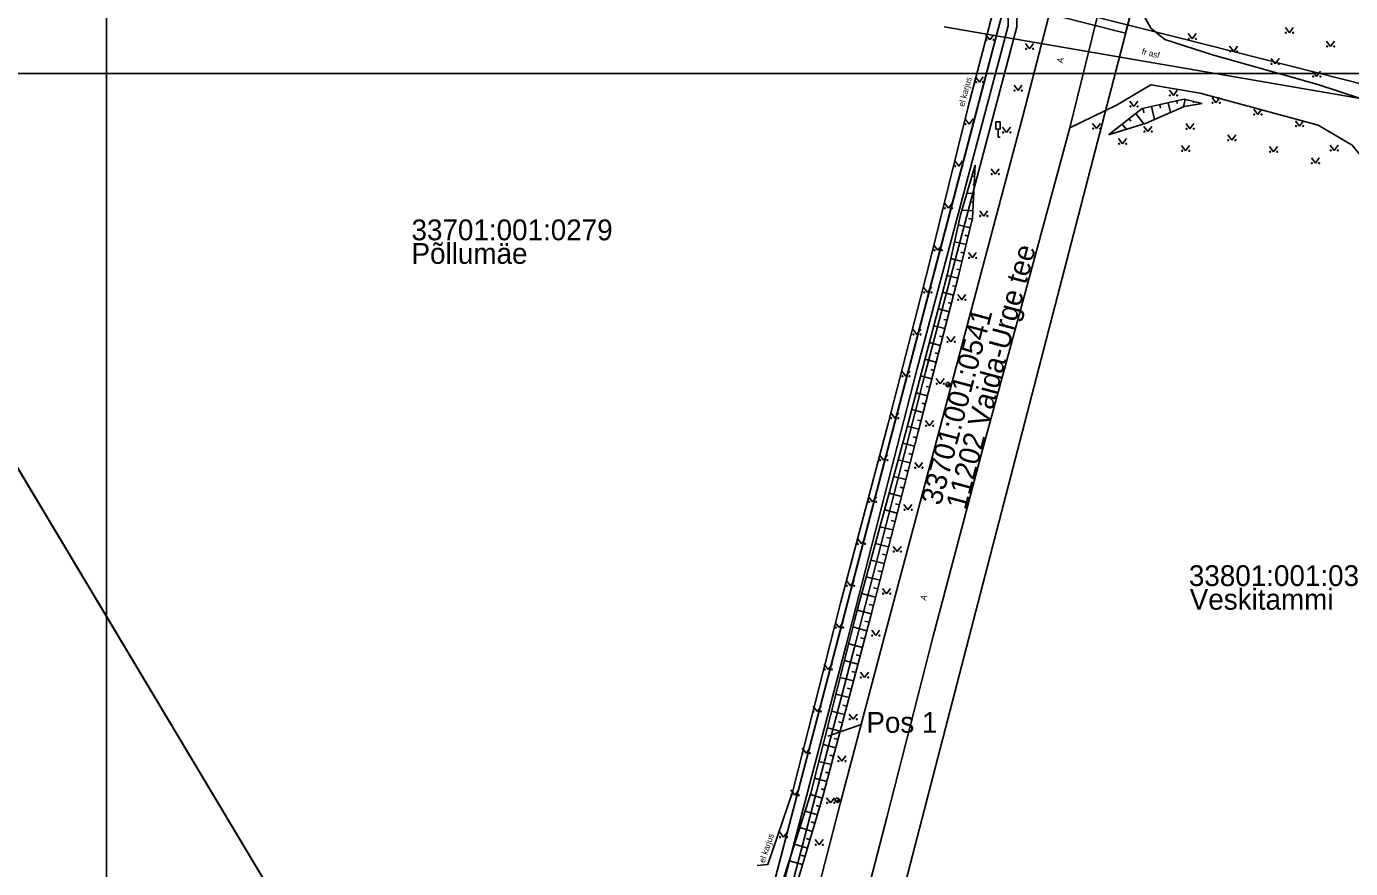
# Model space of a CAD drawing. Extents: x 554947 to 555436, y 6564938 to 6565792.
# Drawn here: x 555042.9 to 555195.6, y 6565056.2 to 6565153.3 of the extents above; entities that cross this region are included whole.
import ezdxf

# ---------------------------------------------------------------- set-up
doc = ezdxf.new("R2010")
doc.units = 0
for name, color, linetype in [('AED', 7, 'Continuous'), ('HALJASTUS', 7, 'Continuous'), ('KASUTUSALA', 7, 'Continuous'), ('KPOHULIIN', 7, 'Continuous'), ('LIIKLUS', 7, 'Continuous'), ('PIIR', 7, 'Continuous'), ('POST', 7, 'Continuous'), ('PR_SIDE', 7, 'Continuous'), ('RELJEEF', 7, 'Continuous'), ('TEE', 7, 'Continuous'), ('VORMISTUS', 7, 'Continuous'), ('VORMISTUS_1', 7, 'Continuous')]:
    doc.layers.add(name, color=color, linetype=linetype)

msp = doc.modelspace()

# ---------------------------------------------------------------- linework, layer by layer
at = {"layer": 'AED'}
msp.add_lwpolyline([(555179.37, 6565300.08), (555180.24, 6565299.85), (555180.75, 6565290.87), (555180.14, 6565280.62), (555178.98, 6565264.79), (555177.98, 6565255.29), (555177.31, 6565249.05), (555173.49, 6565227.42), (555169.73, 6565212.42), (555163.78, 6565189.53), (555156.09, 6565161.76), (555151.43, 6565143.9), (555146.99, 6565125.89), (555142.27, 6565107.51), (555136.77, 6565086.76), (555131.21, 6565064.98), (555128.39, 6565056.62), (555127.14, 6565056.52)], dxfattribs=at)
at = {"layer": 'HALJASTUS'}
for p, q in [((555153.52, 6565152.37), (555153.98, 6565151.76)), ((555153.98, 6565151.76), (555154.43, 6565152.37)), ((555176.86, 6565152.5), (555177.32, 6565151.89)), ((555177.32, 6565151.89), (555177.77, 6565152.5)), ((555188.07, 6565153.19), (555188.53, 6565152.59)), ((555188.53, 6565152.59), (555188.98, 6565153.19)), ((555158.1, 6565151.35), (555158.56, 6565150.74)), ((555158.56, 6565150.74), (555159.01, 6565151.35)), ((555181.64, 6565151.05), (555182.11, 6565150.45)), ((555182.11, 6565150.45), (555182.55, 6565151.05)), ((555192.82, 6565151.63), (555193.28, 6565151.02)), ((555193.28, 6565151.02), (555193.73, 6565151.63)), ((555186.43, 6565149.61), (555186.89, 6565149)), ((555186.89, 6565149), (555187.34, 6565149.61)), ((555152.32, 6565147.52), (555152.79, 6565146.91)), ((555152.79, 6565146.91), (555153.23, 6565147.52)), ((555191.21, 6565148.16), (555191.68, 6565147.55)), ((555191.68, 6565147.55), (555192.12, 6565148.16)), ((555156.78, 6565146.53), (555157.24, 6565145.92)), ((555157.24, 6565145.92), (555157.69, 6565146.53)), ((555174.69, 6565145.97), (555175.15, 6565145.37)), ((555175.15, 6565145.37), (555175.6, 6565145.97)), ((555170.13, 6565144.69), (555170.59, 6565144.09)), ((555170.59, 6565144.09), (555171.04, 6565144.69)), ((555179.61, 6565145.13), (555180.07, 6565144.52)), ((555180.07, 6565144.52), (555180.52, 6565145.13)), ((555184.42, 6565143.79), (555184.89, 6565143.18)), ((555184.89, 6565143.18), (555185.33, 6565143.79)), ((555151.13, 6565142.66), (555151.59, 6565142.05)), ((555151.59, 6565142.05), (555152.04, 6565142.66)), ((555155.46, 6565141.7), (555155.92, 6565141.1)), ((555155.92, 6565141.1), (555156.37, 6565141.7)), ((555165.83, 6565142.14), (555166.3, 6565141.53)), ((555166.3, 6565141.53), (555166.74, 6565142.14)), ((555171.76, 6565141.79), (555172.22, 6565141.19)), ((555172.22, 6565141.19), (555172.67, 6565141.79)), ((555176.61, 6565142.13), (555177.07, 6565141.52)), ((555177.07, 6565141.52), (555177.52, 6565142.13)), ((555189.24, 6565142.44), (555189.7, 6565141.83)), ((555189.7, 6565141.83), (555190.15, 6565142.44)), ((555168.83, 6565140.39), (555169.29, 6565139.79)), ((555169.29, 6565139.79), (555169.74, 6565140.39)), ((555181.43, 6565140.8), (555181.89, 6565140.2)), ((555181.89, 6565140.2), (555182.34, 6565140.8)), ((555176.11, 6565139.58), (555176.57, 6565138.97)), ((555176.57, 6565138.97), (555177.02, 6565139.58)), ((555186.25, 6565139.48), (555186.72, 6565138.87)), ((555186.72, 6565138.87), (555187.16, 6565139.48)), ((555191.07, 6565138.15), (555191.54, 6565137.55)), ((555191.54, 6565137.55), (555191.98, 6565138.15)), ((555193.24, 6565139.63), (555193.71, 6565139.02)), ((555193.71, 6565139.02), (555194.15, 6565139.63)), ((555149.93, 6565137.81), (555150.4, 6565137.2)), ((555150.4, 6565137.2), (555150.84, 6565137.81)), ((555154.13, 6565136.88), (555154.6, 6565136.28)), ((555154.6, 6565136.28), (555155.04, 6565136.88)), ((555148.74, 6565132.95), (555149.2, 6565132.34)), ((555149.2, 6565132.34), (555149.64, 6565132.95)), ((555152.81, 6565132.06), (555153.28, 6565131.45)), ((555153.28, 6565131.45), (555153.72, 6565132.06)), ((555147.54, 6565128.1), (555148, 6565127.49)), ((555148, 6565127.49), (555148.45, 6565128.1)), ((555151.52, 6565127.23), (555151.98, 6565126.62)), ((555151.98, 6565126.62), (555152.42, 6565127.23)), ((555146.34, 6565123.24), (555146.81, 6565122.63)), ((555146.81, 6565122.63), (555147.25, 6565123.24)), ((555150.28, 6565122.39), (555150.74, 6565121.78)), ((555150.74, 6565121.78), (555151.19, 6565122.39)), ((555145.11, 6565118.4), (555145.57, 6565117.79)), ((555145.57, 6565117.79), (555146.02, 6565118.4)), ((555149.04, 6565117.54), (555149.5, 6565116.94)), ((555149.5, 6565116.94), (555149.95, 6565117.54)), ((555143.83, 6565113.56), (555144.29, 6565112.96)), ((555144.29, 6565112.96), (555144.74, 6565113.56)), ((555147.8, 6565112.7), (555148.26, 6565112.09)), ((555148.26, 6565112.09), (555148.71, 6565112.7)), ((555142.55, 6565108.73), (555143.01, 6565108.12)), ((555143.01, 6565108.12), (555143.46, 6565108.73)), ((555146.56, 6565107.86), (555147.02, 6565107.25)), ((555147.02, 6565107.25), (555147.47, 6565107.86)), ((555141.27, 6565103.9), (555141.73, 6565103.29)), ((555141.73, 6565103.29), (555142.18, 6565103.9)), ((555145.32, 6565103.01), (555145.78, 6565102.41)), ((555145.78, 6565102.41), (555146.23, 6565103.01)), ((555139.99, 6565099.06), (555140.45, 6565098.46)), ((555140.45, 6565098.46), (555140.9, 6565099.06)), ((555144.08, 6565098.17), (555144.54, 6565097.56)), ((555144.54, 6565097.56), (555144.99, 6565098.17)), ((555138.71, 6565094.23), (555139.18, 6565093.62)), ((555139.18, 6565093.62), (555139.62, 6565094.23)), ((555142.84, 6565093.32), (555143.3, 6565092.72)), ((555143.3, 6565092.72), (555143.75, 6565093.32)), ((555137.43, 6565089.39), (555137.9, 6565088.79)), ((555137.9, 6565088.79), (555138.34, 6565089.39)), ((555141.6, 6565088.48), (555142.06, 6565087.87)), ((555142.06, 6565087.87), (555142.51, 6565088.48)), ((555136.15, 6565084.56), (555136.62, 6565083.95)), ((555136.62, 6565083.95), (555137.06, 6565084.56)), ((555140.36, 6565083.64), (555140.82, 6565083.03)), ((555140.82, 6565083.03), (555141.27, 6565083.64)), ((555134.88, 6565079.73), (555135.34, 6565079.12)), ((555135.34, 6565079.12), (555135.78, 6565079.73)), ((555139.06, 6565078.81), (555139.52, 6565078.2)), ((555139.52, 6565078.2), (555139.97, 6565078.81)), ((555133.6, 6565074.89), (555134.06, 6565074.29)), ((555134.06, 6565074.29), (555134.51, 6565074.89)), ((555137.75, 6565073.98), (555138.22, 6565073.38)), ((555138.22, 6565073.38), (555138.66, 6565073.98)), ((555132.32, 6565070.06), (555132.78, 6565069.45)), ((555132.78, 6565069.45), (555133.23, 6565070.06)), ((555136.45, 6565069.16), (555136.91, 6565068.55)), ((555136.91, 6565068.55), (555137.36, 6565069.16)), ((555131.04, 6565065.23), (555131.5, 6565064.62)), ((555131.5, 6565064.62), (555131.95, 6565065.23)), ((555135.14, 6565064.33), (555135.61, 6565063.72)), ((555135.61, 6565063.72), (555136.05, 6565064.33)), ((555129.73, 6565060.4), (555130.19, 6565059.79)), ((555130.19, 6565059.79), (555130.64, 6565060.4)), ((555133.84, 6565059.5), (555134.3, 6565058.89)), ((555134.3, 6565058.89), (555134.75, 6565059.5))]:
    msp.add_line(p, q, dxfattribs=at)
for centre in [(555176.92, 6565151.89), (555177.75, 6565151.89), (555188.13, 6565152.59), (555188.96, 6565152.59), (555153.58, 6565151.76), (555154.41, 6565151.76), (555158.16, 6565150.74), (555158.99, 6565150.74), (555181.71, 6565150.45), (555182.53, 6565150.45), (555192.88, 6565151.02), (555193.71, 6565151.02), (555186.49, 6565149), (555187.32, 6565149), (555191.28, 6565147.55), (555192.11, 6565147.55), (555152.39, 6565146.91), (555153.21, 6565146.91), (555156.84, 6565145.92), (555157.67, 6565145.92), (555174.75, 6565145.37), (555175.58, 6565145.37), (555179.67, 6565144.52), (555180.5, 6565144.52), (555170.19, 6565144.09), (555171.02, 6565144.09), (555184.49, 6565143.18), (555185.32, 6565143.18), (555151.19, 6565142.05), (555152.02, 6565142.05), (555165.9, 6565141.53), (555166.72, 6565141.53), (555171.82, 6565141.19), (555172.65, 6565141.19), (555176.67, 6565141.52), (555177.5, 6565141.52), (555189.3, 6565141.83), (555190.13, 6565141.83), (555155.52, 6565141.1), (555156.35, 6565141.1), (555168.89, 6565139.79), (555169.72, 6565139.79), (555181.49, 6565140.2), (555182.32, 6565140.2), (555176.17, 6565138.97), (555177, 6565138.97), (555186.31, 6565138.87), (555187.14, 6565138.87), (555193.31, 6565139.02), (555194.13, 6565139.02), (555149.99, 6565137.2), (555150.82, 6565137.2), (555191.14, 6565137.55), (555191.96, 6565137.55), (555154.2, 6565136.28), (555155.03, 6565136.28), (555148.8, 6565132.34), (555149.63, 6565132.34), (555152.87, 6565131.45), (555153.7, 6565131.45), (555147.6, 6565127.49), (555148.43, 6565127.49), (555151.58, 6565126.62), (555152.41, 6565126.62), (555146.41, 6565122.63), (555147.24, 6565122.63), (555150.34, 6565121.78), (555151.17, 6565121.78), (555145.17, 6565117.79), (555146, 6565117.79), (555149.1, 6565116.94), (555149.93, 6565116.94), (555143.89, 6565112.96), (555144.72, 6565112.96), (555147.86, 6565112.09), (555148.69, 6565112.09), (555142.61, 6565108.12), (555143.44, 6565108.12), (555146.62, 6565107.25), (555147.45, 6565107.25), (555141.33, 6565103.29), (555142.16, 6565103.29), (555145.38, 6565102.41), (555146.21, 6565102.41), (555140.05, 6565098.46), (555140.88, 6565098.46), (555144.14, 6565097.56), (555144.97, 6565097.56), (555138.77, 6565093.62), (555139.6, 6565093.62), (555142.9, 6565092.72), (555143.73, 6565092.72), (555137.5, 6565088.79), (555138.32, 6565088.79), (555141.66, 6565087.87), (555142.49, 6565087.87), (555136.22, 6565083.95), (555137.05, 6565083.95), (555140.42, 6565083.03), (555141.25, 6565083.03), (555134.94, 6565079.12), (555135.77, 6565079.12), (555139.12, 6565078.2), (555139.95, 6565078.2), (555133.66, 6565074.29), (555134.49, 6565074.29), (555137.82, 6565073.38), (555138.64, 6565073.38), (555132.38, 6565069.45), (555133.21, 6565069.45), (555136.51, 6565068.55), (555137.34, 6565068.55), (555131.1, 6565064.62), (555131.93, 6565064.62), (555135.21, 6565063.72), (555136.03, 6565063.72), (555129.79, 6565059.79), (555130.62, 6565059.79), (555133.9, 6565058.89), (555134.73, 6565058.89)]:
    msp.add_circle(centre, 0.055, dxfattribs=at)
at = {"layer": 'KASUTUSALA'}
for points in [[(555181.45, 6565256.37), (555178.9, 6565239.74), (555178.02, 6565234.84), (555174.64, 6565220.29), (555166.41, 6565188.7), (555161.68, 6565171.12), (555158.19, 6565157.5), (555170.13, 6565154.48), (555169.63, 6565152.55), (555157.92, 6565155.51), (555157.54, 6565155.38), (555157.27, 6565155.02), (555157.09, 6565154.42), (555157.08, 6565153.27), (555146.55, 6565113.44), (555138.36, 6565081.69), (555129.03, 6565046.1)], [(555127.06, 6565046.78), (555141, 6565099.93), (555152.73, 6565144.63), (555155.08, 6565153.61), (555155.89, 6565156.67), (555156.91, 6565160.58), (555162.41, 6565181.55), (555172.65, 6565220.57), (555172.7, 6565220.76), (555176.93, 6565240.07), (555176.94, 6565240.14), (555179.22, 6565254.85)]]:
    msp.add_lwpolyline(points, dxfattribs=at)
at = {"layer": 'KPOHULIIN'}
msp.add_lwpolyline([(555148.7, 6565153.26), (555226.64, 6565139.85), (555319.31, 6565121.59)], dxfattribs=at)
at = {"layer": 'LIIKLUS'}
for p, q in [((555154.68, 6565142.31), (555154.68, 6565141.46)), ((555155.18, 6565142.31), (555154.68, 6565142.31)), ((555155.18, 6565141.46), (555154.68, 6565141.46)), ((555154.93, 6565141.46), (555154.93, 6565140.56)), ((555155.18, 6565142.31), (555155.18, 6565141.46)), ((555155.18, 6565140.56), (555154.93, 6565140.56))]:
    msp.add_line(p, q, dxfattribs=at)
at = {"layer": 'PIIR'}
msp.add_lwpolyline([(554962.55, 6565234.93), (555180.26, 6565306.43), (555180.8, 6565287.7), (555180.41, 6565269.99), (555179.22, 6565254.85), (555176.93, 6565240.09), (555172.7, 6565220.76), (555117.14, 6565008.97), (555108.27, 6564991.27)], close=True, dxfattribs=at)
for points in [[(555195.28, 6565271.63), (555191.64, 6565237.48), (555173.84, 6565168.77), (555173.21, 6565166.35), (555172.58, 6565163.93), (555140.74, 6565041.04), (555133.32, 6565012.53), (555119.68, 6564972.95), (555107.79, 6564965.53), (555093.78, 6564958.98), (555080.97, 6564954.71), (555029.59, 6564944.2)], [(555029.59, 6564962.19), (555076.32, 6564971.61), (555087.28, 6564975.26), (555098.22, 6564980.37), (555106.03, 6564987.06), (555108.27, 6564991.27), (555117.14, 6565008.97), (555172.7, 6565220.76), (555176.93, 6565240.09), (555179.22, 6565254.85)], [(555272.01, 6565013.37), (555140.74, 6565041.04), (555172.58, 6565163.93), (555173.21, 6565166.35), (555225.89, 6565157.13), (555231.12, 6565150.64), (555239.11, 6565139), (555273.15, 6565087.34), (555275.41, 6565088.83), (555288.85, 6565092.31), (555289.83, 6565088.53), (555290.17, 6565088.22)], [(555029.59, 6565122.84), (555108.27, 6564991.27), (555106.03, 6564987.06), (555098.22, 6564980.37), (555087.28, 6564975.26), (555076.32, 6564971.61), (555029.59, 6564962.19)]]:
    msp.add_lwpolyline(points, dxfattribs=at)
at = {"layer": 'POST'}
for p, q in [((555148.99, 6565111.82), (555149.35, 6565112.17)), ((555136.2, 6565063.85), (555136.55, 6565064.2))]:
    msp.add_line(p, q, dxfattribs=at)
for centre in [(555149.17, 6565112), (555136.38, 6565064.03)]:
    msp.add_circle(centre, 0.25, dxfattribs=at)
for centre, radius, start, end in [((555149.17, 6565112), 0.225, 224.8541, 45.0356), ((555149.17, 6565112), 0.2, 224.8427, 45.047), ((555149.17, 6565112), 0.175, 224.8281, 45.0616), ((555149.17, 6565112), 0.15, 224.8087, 45.081), ((555149.17, 6565112), 0.125, 224.7814, 45.1083), ((555149.17, 6565112), 0.1, 224.7406, 45.1491), ((555149.17, 6565112), 0.075, 224.6725, 45.2172), ((555149.17, 6565112), 0.05, 224.5363, 45.3534), ((555149.17, 6565112), 0.025, 224.1278, 45.7619), ((555136.38, 6565064.03), 0.225, 224.8541, 45.0356), ((555136.38, 6565064.03), 0.2, 224.8427, 45.047), ((555136.38, 6565064.03), 0.175, 224.8281, 45.0616), ((555136.38, 6565064.03), 0.15, 224.8087, 45.081), ((555136.38, 6565064.03), 0.125, 224.7814, 45.1083), ((555136.38, 6565064.03), 0.1, 224.7406, 45.1491), ((555136.38, 6565064.03), 0.075, 224.6725, 45.2172), ((555136.38, 6565064.03), 0.05, 224.5363, 45.3534), ((555136.38, 6565064.03), 0.025, 224.1278, 45.7619)]:
    msp.add_arc(centre, radius, start, end, dxfattribs=at)
at = {"layer": 'PR_SIDE'}
for points in [[(555210.99, 6564988.67), (555132.01, 6564980.72), (555127.54, 6564982.26), (555122.65, 6564985.01), (555110.84, 6564991.67), (555110.65, 6564992.61), (555118.47, 6565008.13), (555128.06, 6565046.35), (555137.4, 6565081.94), (555145.58, 6565113.69), (555156.08, 6565153.41), (555156.09, 6565155.11), (555156.86, 6565156.34), (555160.71, 6565171.37), (555165.44, 6565188.96), (555173.67, 6565220.53), (555177.04, 6565235.04), (555177.91, 6565239.91), (555180.46, 6565256.48)], [(555296.81, 6565115.61), (555286.61, 6565117.39), (555285.81, 6565118.25), (555287.84, 6565125.96), (555287.1, 6565126.92), (555245.34, 6565135.12), (555231.31, 6565137.91), (555222.99, 6565144.57), (555217.72, 6565147.16), (555203.94, 6565144.9), (555175.82, 6565152.01), (555157.88, 6565156.55), (555156.92, 6565156.24), (555156.09, 6565155.11)]]:
    msp.add_lwpolyline(points, dxfattribs=at)
at = {"layer": 'RELJEEF'}
for p, q in [((555173.6, 6565144.29), (555173.68, 6565143.9)), ((555174.57, 6565144.51), (555174.82, 6565143.39)), ((555175.55, 6565144.73), (555175.61, 6565144.45)), ((555176.52, 6565144.88), (555176.32, 6565144.04)), ((555177.5, 6565144.65), (555177.47, 6565144.52)), ((555170.84, 6565143.27), (555171.76, 6565142.09)), ((555171.65, 6565143.86), (555171.76, 6565143.35)), ((555172.62, 6565144.07), (555172.96, 6565142.58)), ((555168.47, 6565141.44), (555168.53, 6565141.35)), ((555169.26, 6565142.05), (555169.72, 6565141.46)), ((555170.05, 6565142.66), (555170.25, 6565142.4)), ((555152.29, 6565137.05), (555152.27, 6565137.06)), ((555152.24, 6565136.06), (555151.93, 6565136.07)), ((555152.14, 6565134.06), (555151.33, 6565134.1)), ((555152.19, 6565135.06), (555152.02, 6565135.07)), ((555152.04, 6565132.06), (555150.74, 6565132.13)), ((555152.09, 6565133.06), (555151.78, 6565133.08)), ((555151.97, 6565131.07), (555151.54, 6565131.17)), ((555151.73, 6565130.09), (555150.32, 6565130.44)), ((555151.5, 6565129.12), (555151.08, 6565129.22)), ((555151.26, 6565128.15), (555149.9, 6565128.48)), ((555150.79, 6565126.21), (555149.47, 6565126.53)), ((555151.02, 6565127.18), (555150.62, 6565127.28)), ((555150.31, 6565124.26), (555149.04, 6565124.59)), ((555150.55, 6565125.24), (555150.16, 6565125.33)), ((555150.06, 6565123.3), (555149.68, 6565123.4)), ((555149.81, 6565122.33), (555148.53, 6565122.66)), ((555149.56, 6565121.36), (555149.17, 6565121.46)), ((555149.31, 6565120.39), (555148.02, 6565120.73)), ((555148.81, 6565118.46), (555147.51, 6565118.79)), ((555149.06, 6565119.42), (555148.67, 6565119.52)), ((555148.3, 6565116.52), (555147, 6565116.86)), ((555148.55, 6565117.49), (555148.17, 6565117.59)), ((555148.05, 6565115.55), (555147.66, 6565115.65)), ((555147.8, 6565114.58), (555146.49, 6565114.92)), ((555147.55, 6565113.62), (555147.16, 6565113.72)), ((555147.3, 6565112.65), (555145.98, 6565112.99)), ((555146.8, 6565110.71), (555145.48, 6565111.06)), ((555147.05, 6565111.68), (555146.65, 6565111.78)), ((555146.55, 6565109.74), (555146.15, 6565109.85)), ((555146.3, 6565108.78), (555144.97, 6565109.12)), ((555146.05, 6565107.81), (555145.65, 6565107.91)), ((555145.79, 6565106.84), (555144.46, 6565107.19)), ((555145.3, 6565104.9), (555143.93, 6565105.25)), ((555145.54, 6565105.87), (555145.14, 6565105.98)), ((555144.8, 6565102.97), (555143.41, 6565103.32)), ((555145.05, 6565103.94), (555144.63, 6565104.04)), ((555144.55, 6565102), (555144.13, 6565102.11)), ((555144.3, 6565101.03), (555142.88, 6565101.39)), ((555144.05, 6565100.06), (555143.62, 6565100.17)), ((555143.8, 6565099.09), (555142.36, 6565099.46)), ((555143.3, 6565097.16), (555141.83, 6565097.53)), ((555143.55, 6565098.12), (555143.11, 6565098.24)), ((555142.8, 6565095.22), (555141.31, 6565095.6)), ((555143.05, 6565096.19), (555142.61, 6565096.3)), ((555142.55, 6565094.25), (555142.1, 6565094.37)), ((555142.3, 6565093.28), (555140.78, 6565093.67)), ((555142.05, 6565092.31), (555141.59, 6565092.43)), ((555141.8, 6565091.35), (555140.26, 6565091.74)), ((555141.3, 6565089.41), (555139.73, 6565089.81)), ((555141.55, 6565090.38), (555141.08, 6565090.5)), ((555140.8, 6565087.47), (555139.2, 6565087.88)), ((555141.05, 6565088.44), (555140.58, 6565088.56)), ((555140.55, 6565086.5), (555140.07, 6565086.63)), ((555140.3, 6565085.54), (555138.68, 6565085.95)), ((555140.05, 6565084.57), (555139.57, 6565084.7)), ((555139.79, 6565083.6), (555138.19, 6565084.03)), ((555139.28, 6565081.67), (555137.7, 6565082.09)), ((555139.54, 6565082.64), (555139.06, 6565082.76)), ((555138.77, 6565079.74), (555137.21, 6565080.15)), ((555139.03, 6565080.7), (555138.55, 6565080.83)), ((555138.51, 6565078.77), (555138.05, 6565078.89)), ((555138.26, 6565077.8), (555136.72, 6565078.21)), ((555137.75, 6565075.87), (555136.23, 6565076.27)), ((555138, 6565076.84), (555137.54, 6565076.96)), ((555137.23, 6565073.94), (555135.73, 6565074.33)), ((555137.49, 6565074.9), (555137.04, 6565075.02)), ((555136.98, 6565072.97), (555136.53, 6565073.09)), ((555136.72, 6565072), (555135.24, 6565072.39)), ((555136.47, 6565071.04), (555136.03, 6565071.15)), ((555136.21, 6565070.07), (555134.75, 6565070.46)), ((555135.7, 6565068.14), (555134.26, 6565068.52)), ((555135.95, 6565069.1), (555135.52, 6565069.22)), ((555135.19, 6565066.2), (555133.77, 6565066.58)), ((555135.44, 6565067.17), (555135.01, 6565067.28)), ((555134.93, 6565065.24), (555134.51, 6565065.35)), ((555134.66, 6565064.27), (555133.28, 6565064.68)), ((555134.38, 6565063.31), (555133.96, 6565063.44)), ((555134.09, 6565062.36), (555132.67, 6565062.78)), ((555133.52, 6565060.44), (555132.06, 6565060.87)), ((555133.81, 6565061.4), (555133.38, 6565061.53)), ((555132.95, 6565058.52), (555131.46, 6565058.97)), ((555133.24, 6565059.48), (555132.79, 6565059.61)), ((555132.67, 6565057.56), (555132.21, 6565057.7)), ((555132.38, 6565056.6), (555130.85, 6565057.06))]:
    msp.add_line(p, q, dxfattribs=at)
for points in [[(555167.67, 6565140.83), (555171.57, 6565143.84), (555176.38, 6565144.92), (555178.46, 6565144.42)], [(555167.67, 6565140.83), (555172, 6565142.16), (555176.4, 6565144.07), (555178.46, 6565144.42)], [(555119.66, 6565010.32), (555123.71, 6565025.31), (555129.01, 6565045.27), (555134.76, 6565064.61), (555140.24, 6565085.3), (555145.72, 6565106.56), (555150.38, 6565124.53), (555152, 6565131.19), (555152.3, 6565137.3)], [(555119.66, 6565010.32), (555122.57, 6565025.47), (555127.46, 6565046.43), (555133.34, 6565064.86), (555138.64, 6565085.82), (555144.36, 6565106.83), (555149.09, 6565124.76), (555150.58, 6565131.59), (555152.3, 6565137.3)]]:
    msp.add_lwpolyline(points, dxfattribs=at)
at = {"layer": 'TEE'}
for points in [[(555183.59, 6565248.99), (555179.7, 6565227.86), (555175.39, 6565210.51), (555169.43, 6565187.48), (555162.32, 6565160.51), (555157.77, 6565142.96), (555152.67, 6565123.75), (555148, 6565106.07), (555142.31, 6565084.71), (555136.78, 6565063.94), (555131.82, 6565044.7), (555126.53, 6565024.44), (555123, 6565010.82), (555119.08, 6564999.09), (555116.16, 6564993.2), (555108.26, 6564982.26)], [(555115, 6564980.21), (555119.47, 6564986.79), (555121.43, 6564990.44), (555124.13, 6564996.67), (555128.45, 6565009.12), (555131.98, 6565022.77), (555137.23, 6565043.21), (555142.09, 6565062.04), (555147.46, 6565082.98), (555153.12, 6565104.46), (555157.98, 6565122.31), (555163.2, 6565141.62), (555168.3, 6565162.21), (555168.74, 6565163.56), (555174.48, 6565185.52), (555180.71, 6565208.97), (555185.09, 6565226.84), (555186.8, 6565233.51), (555187.91, 6565235.65)], [(555205.86, 6565133.78), (555206.22, 6565135.82), (555207.41, 6565138.33), (555209.43, 6565140.1), (555211.79, 6565141.19), (555217.23, 6565143.07), (555216.44, 6565145.53), (555210.77, 6565144.28), (555206.51, 6565143.56), (555202.01, 6565143.28), (555191.83, 6565146.63), (555179.65, 6565150.04), (555174.16, 6565151.8), (555172.54, 6565153.14), (555170.21, 6565157.38), (555168.46, 6565160.67), (555168.3, 6565162.21)], [(555163.2, 6565141.62), (555168.59, 6565144.25), (555172.57, 6565146.6), (555178.23, 6565145.61), (555191.85, 6565141.95), (555195.78, 6565139.63), (555200.74, 6565133.54)]]:
    msp.add_lwpolyline(points, dxfattribs=at)
at = {"layer": 'VORMISTUS'}
msp.add_line((555135.31, 6565071.41), (555139.25, 6565072.81), dxfattribs=at)
msp.add_lwpolyline([(555217.09, 6564974.91), (555052.09, 6564974.91), (555052.09, 6565184.91), (555217.09, 6565184.91)], close=True, dxfattribs=at)
at = {"layer": 'VORMISTUS_1'}
msp.add_lwpolyline([(555035.19, 6565444.91), (555245.19, 6565444.91), (555245.19, 6565147.91), (555035.19, 6565147.91)], close=True, dxfattribs=at)

# ---------------------------------------------------------------- texts
at = {"layer": 'AED'}
for rotation, p in [(75.2255, (555151.02, 6565144.01)), (71.28, (555127.99, 6565056.75))]:
    msp.add_text('el karjus', height=0.7, rotation=rotation, dxfattribs=at).set_placement(p)
at = {"layer": 'PIIR'}
for s, p in [('33701:001:0279', (555087.27, 6565128.65)), ('Põllumäe', (555087.27, 6565125.93)), ('33801:001:0392', (555176.94, 6565088.75)), ('Veskitammi', (555177.04, 6565086.02))]:
    msp.add_text(s, height=2.4, dxfattribs=at).set_placement(p)
for s, p in [('11202 Vaida-Urge tee', (555151.19, 6565097.44)), ('33701:001:0541', (555148.31, 6565097.95))]:
    msp.add_text(s, height=2.4, rotation=75.0195, dxfattribs=at).set_placement(p)
at = {"layer": 'TEE'}
for s, rotation, p in [('fr asf', 346.2302, (555171.46, 6565150.13)), ('A', 75.6331, (555162.37, 6565149.03)), ('A', 71.8158, (555146.58, 6565087.03))]:
    msp.add_text(s, height=0.7, rotation=rotation, dxfattribs=at).set_placement(p)
at = {"layer": 'VORMISTUS'}
msp.add_text('Pos 1', height=2.4, dxfattribs=at).set_placement((555139.74, 6565071.82))

doc.saveas('drawing.dxf')
